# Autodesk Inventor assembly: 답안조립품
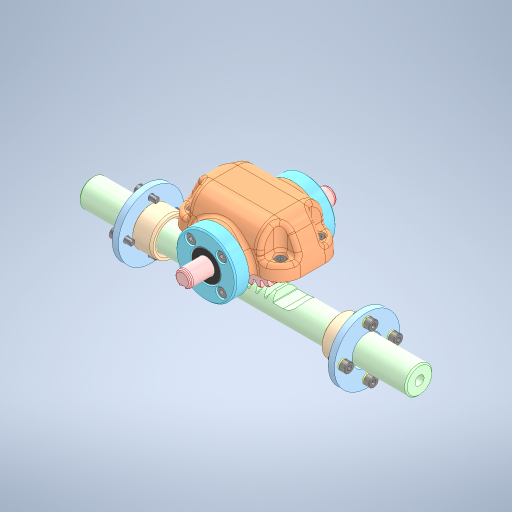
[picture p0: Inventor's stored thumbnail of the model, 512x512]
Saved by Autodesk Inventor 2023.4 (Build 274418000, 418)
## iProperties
Created: 2024-06
Part Number: 답안조립품
Document SubType Name: Assembly
Designer: user
Author: user
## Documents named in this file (13)
- C:\Users\user\Desktop\740604V1002\답안조립품.iam
- C:\Users\user\Desktop\740604V1002\본체.ipt
- C:\Users\user\Desktop\740604V1002\깊은 홈 볼 베어링 6901.ipt
- C:\Users\user\Desktop\740604V1002\랙.ipt
- C:\Users\user\Desktop\740604V1002\베어링 커버.ipt
- C:\Users\user\Desktop\740604V1002\부시 커버.ipt
- C:\Users\user\Desktop\740604V1002\스프링 와셔 M4.ipt
- C:\Users\user\Desktop\740604V1002\오일레스 부시.ipt
- C:\Users\user\Desktop\740604V1002\오일실 12 22 7.ipt
- C:\Users\user\Desktop\740604V1002\윗커버.ipt
- C:\Users\user\Desktop\740604V1002\육각 소켓 머리 볼트 M4x10.ipt
- C:\Users\user\Desktop\740604V1002\칼라.ipt
- C:\Users\user\Desktop\740604V1002\피니언.ipt
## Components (1 placed, 1 different names)
1. 피니언:1 — 플러쉬:2
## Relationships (1: Flush 1)
- 플러쉬:2 [Flush]: 피니언:1
